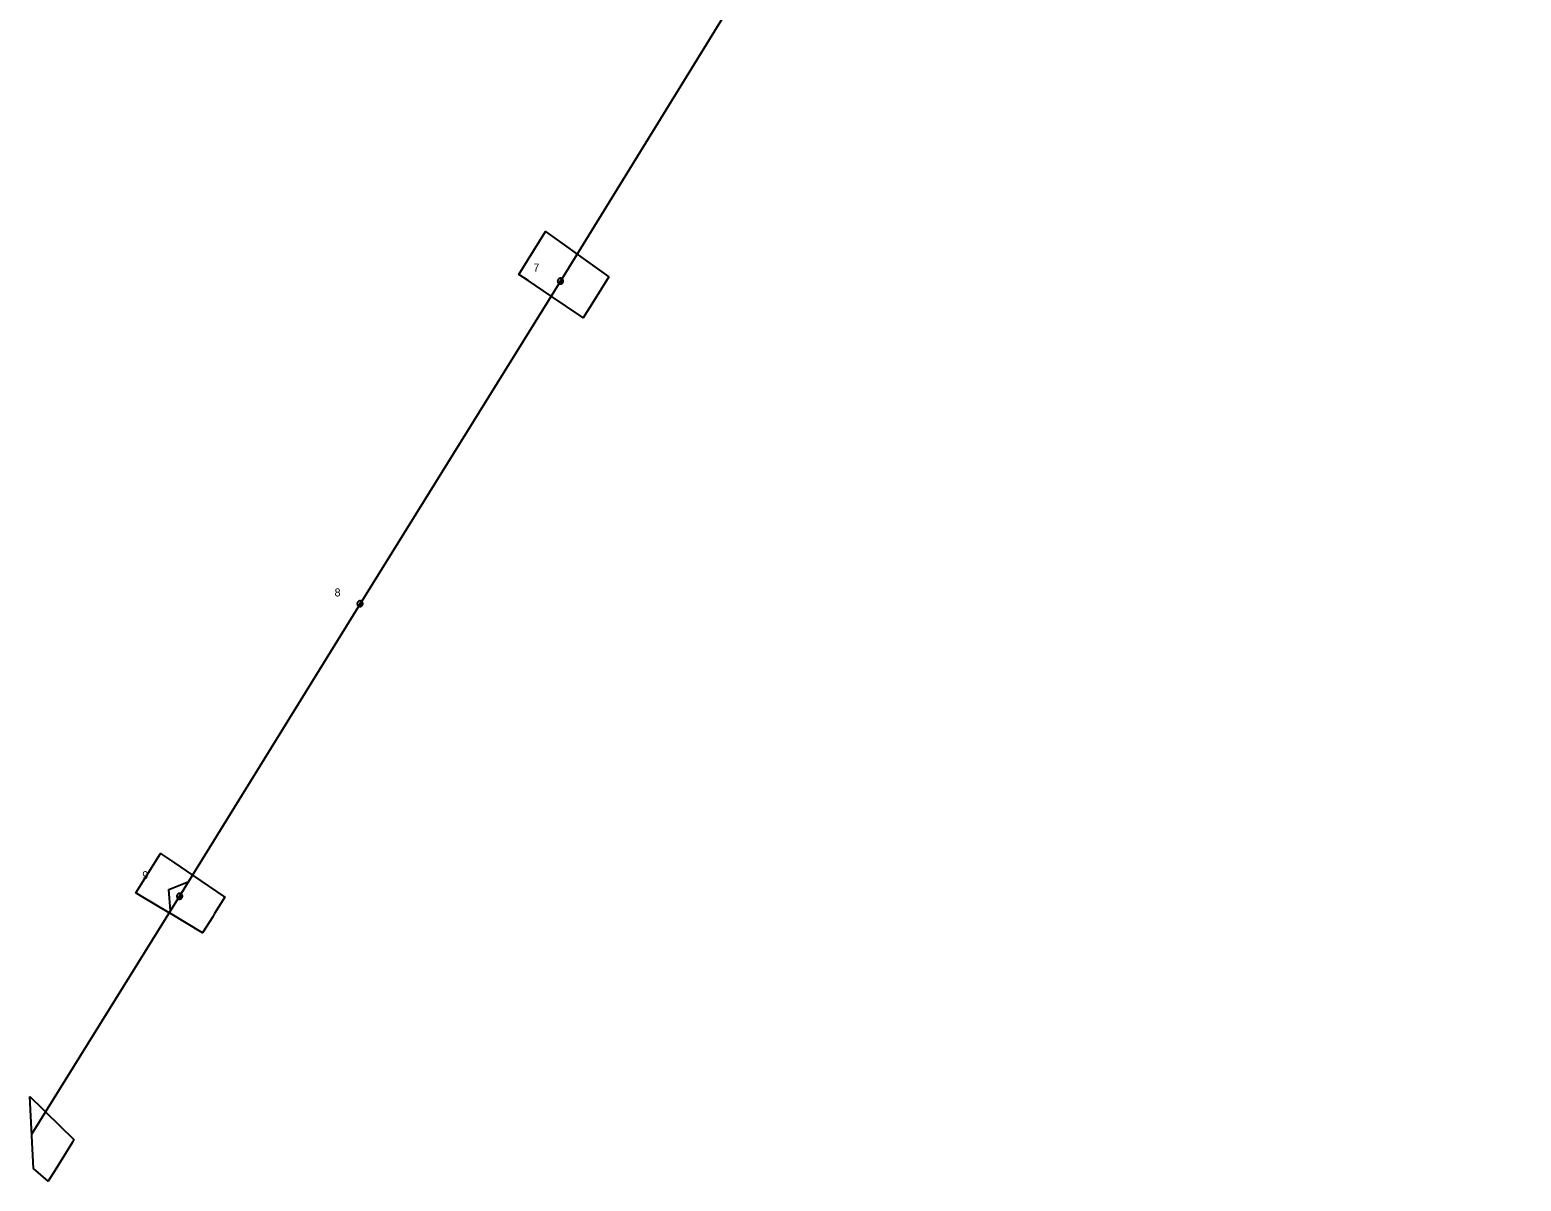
# Model space of a CAD drawing. Extents: x -545588 to -543214, y -1196037 to -1194452.
# Drawn here: x -545558 to -545231.8, y -1195446 to -1195194.1 of the extents above; entities that cross this region are included whole.
import ezdxf

# ---------------------------------------------------------------- set-up
doc = ezdxf.new("R2010")
doc.units = 0
for name, color, linetype in [('DOPLŇ_POPISY', 7, 'Continuous'), ('ELE_EON', 7, 'Continuous'), ('ELE_EON_POPIS', 7, 'Continuous'), ('POL_ZNAČKA_PRACOVNÍ', 7, 'Continuous'), ('Vrstva 18', 7, 'Continuous'), ('Vrstva 35', 7, 'Continuous')]:
    doc.layers.add(name, color=color, linetype=linetype)

# ---------------------------------------------------------------- blocks, each defined once
blk = doc.blocks.new('VN860')
at = {"layer": 'POL_ZNAČKA_PRACOVNÍ'}
for points in [[(-3.74, 0), (0.01, 2.82)], [(0.01, 2.82), (3.76, 0)]]:
    blk.add_lwpolyline(points, dxfattribs=at)
blk = doc.blocks.new('VN440')
at = {"layer": 'ELE_EON_POPIS'}
for points in [[(1.22, 0), (1.21, 0.13), (1.19, 0.25), (1.16, 0.38), (1.11, 0.5), (1.05, 0.61), (0.98, 0.72), (0.9, 0.82), (0.81, 0.91), (0.71, 0.99), (0.6, 1.06), (0.49, 1.12), (0.37, 1.16), (0.25, 1.2), (0.12, 1.22), (-0.01, 1.22), (-0.14, 1.22), (-0.26, 1.2), (-0.39, 1.16), (-0.51, 1.12), (-0.62, 1.06), (-0.73, 0.99), (-0.83, 0.91), (-0.92, 0.82), (-1, 0.72), (-1.07, 0.61), (-1.13, 0.5), (-1.18, 0.38), (-1.21, 0.25), (-1.23, 0.13), (-1.24, 0), (-1.23, -0.13), (-1.21, -0.26), (-1.18, -0.38), (-1.13, -0.5), (-1.07, -0.62), (-1, -0.73), (-0.92, -0.83), (-0.83, -0.92), (-0.73, -1), (-0.62, -1.07), (-0.51, -1.13), (-0.39, -1.17), (-0.26, -1.2), (-0.14, -1.23), (-0.01, -1.23), (0.12, -1.23), (0.25, -1.2), (0.37, -1.17), (0.49, -1.13), (0.6, -1.07), (0.71, -1), (0.81, -0.92), (0.9, -0.83), (0.98, -0.73), (1.05, -0.62), (1.11, -0.5), (1.16, -0.38), (1.19, -0.26), (1.21, -0.13), (1.22, 0)], [(-1.24, 0), (1.22, 0)], [(-1.18, -0.34), (1.1, -0.34)], [(-1.01, -0.63), (0.97, -0.63)], [(-0.74, -0.92), (0.68, -0.92)]]:
    blk.add_lwpolyline(points, dxfattribs=at)

msp = doc.modelspace()

# ---------------------------------------------------------------- linework, layer by layer
at = {"layer": 'ELE_EON'}
msp.add_lwpolyline([(-545231.84, -1194976.41), (-545288.22, -1195044.64), (-545343.3, -1195111.41), (-545397.6, -1195177.04), (-545441.95, -1195249.1), (-545485.78, -1195319.69), (-545525.23, -1195383.69), (-545557.58, -1195435.71)], dxfattribs=at)
at = {"layer": 'Vrstva 35'}
for points in [[(-545431.38, -1195248.15), (-545434.72, -1195253.57), (-545436.95, -1195257.17), (-545437.5, -1195256.8), (-545444, -1195252.4), (-545449.01, -1195249.01), (-545451.04, -1195247.63), (-545449.18, -1195244.63), (-545445.24, -1195238.22), (-545441.15, -1195241.15), (-545438.31, -1195243.18), (-545437.5, -1195243.76)], [(-545517.59, -1195387.5), (-545518, -1195388.17), (-545520.2, -1195391.71), (-545527.23, -1195387.5), (-545527.5, -1195387.34), (-545533.66, -1195383.66), (-545534.8, -1195382.98), (-545532.46, -1195379.22), (-545529.44, -1195374.31), (-545526.39, -1195376.39), (-545522.41, -1195379.11), (-545515.38, -1195383.9)], [(-545558, -1195427.48), (-545555.21, -1195430.21), (-545554.56, -1195430.85), (-545548.34, -1195436.94), (-545548.69, -1195437.5), (-545552.34, -1195443.38), (-545554, -1195446.03), (-545557.2, -1195443.26)]]:
    msp.add_lwpolyline(points, close=True, dxfattribs=at)

# ---------------------------------------------------------------- block references
at = {"layer": 'DOPLŇ_POPISY', "xscale": 0.5}
for p, yscale, rotation in [((-545441.95, -1195249.1), 0.5, 58.16335559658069), ((-545485.78, -1195319.69), 0.5, 58.34994169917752), ((-545525.23, -1195383.69), 0.49999999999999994, 58.12154437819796)]:
    msp.add_blockref('VN440', p, dxfattribs=dict(at, yscale=yscale, rotation=rotation))
at = {"layer": 'Vrstva 18', "rotation": 58.12190834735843}
msp.add_blockref('VN860', (-545525.23, -1195383.69), dxfattribs=at)

# ---------------------------------------------------------------- texts
at = {"layer": 'POL_ZNAČKA_PRACOVNÍ'}
for s, p in [('7', (-545447.88, -1195247.03)), ('8', (-545491.35, -1195318.1)), ('9', (-545533.4, -1195379.96))]:
    msp.add_text(s, height=1.75, dxfattribs=at).set_placement(p)

doc.saveas('drawing.dxf')
